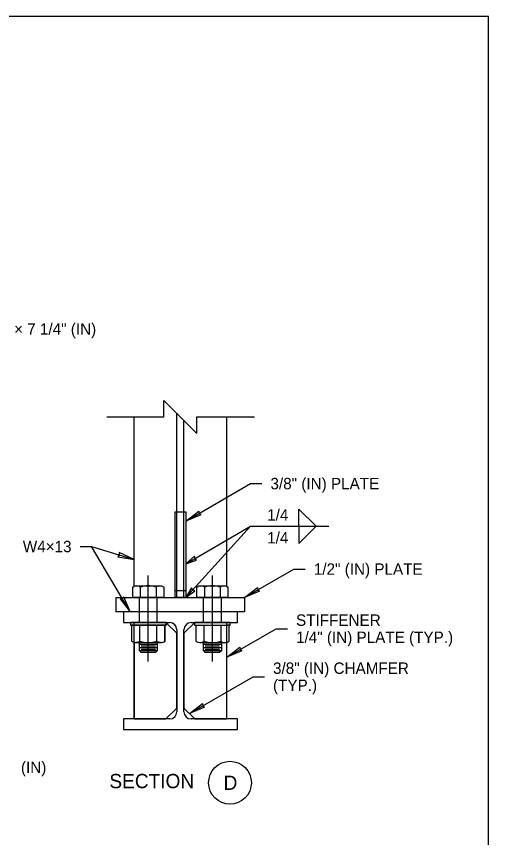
# Model space of a CAD drawing. Extents: x 99862 to 103151, y 100000 to 108076.
# Drawn here: x 102488 to 103151, y 103925 to 105076 of the extents above; entities that cross this region are included whole.
import ezdxf

# ---------------------------------------------------------------- set-up
doc = ezdxf.new("R2010")
doc.units = 0
for name, color, linetype in [('Level 1', 7, 'Continuous'), ('Level 13', 7, 'Continuous'), ('Level 15', 7, 'Continuous'), ('Level 20', 7, 'Continuous'), ('Level 30', 7, 'Continuous'), ('Level 34', 7, 'Continuous'), ('Level 35', 7, 'Continuous'), ('Level 36', 7, 'Continuous'), ('Level 60', 7, 'Continuous'), ('Level 9', 7, 'Continuous')]:
    doc.layers.add(name, color=color, linetype=linetype)

msp = doc.modelspace()

# ---------------------------------------------------------------- linework, layer by layer
at = {"layer": 'Level 1'}
msp.add_lwpolyline([(99862, 102999.5), (103151, 102999.5), (103151, 105075.5), (99862, 105075.5)], close=True, dxfattribs=at)
at = {"layer": 'Level 13'}
for p, q in [((102653.5, 104276.7), (102653.5, 104514.2)), ((102783.5, 104276.6), (102783.5, 104514.2)), ((102798.5, 104241), (102638.5, 104241)), ((102638.5, 104241), (102638.5, 104226)), ((102798.5, 104226), (102798.5, 104241)), ((102638.5, 104226), (102703.5, 104226)), ((102653.5, 104226), (102698.3, 104226)), ((102698.3, 104226), (102713.5, 104211)), ((102738.7, 104226), (102723.5, 104211)), ((102733.5, 104226), (102798.5, 104226)), ((102783.5, 104226), (102738.7, 104226)), ((102783.5, 104091), (102783.5, 104226)), ((102713.5, 104216), (102713.5, 104101)), ((102713.5, 104211), (102713.5, 104106)), ((102723.5, 104101), (102723.5, 104216)), ((102723.5, 104211), (102723.5, 104106)), ((102653.5, 104091), (102653.5, 104198.2)), ((102713.5, 104106), (102698.3, 104091)), ((102723.5, 104106), (102738.7, 104091)), ((102703.5, 104091), (102638.5, 104091)), ((102638.5, 104091), (102638.5, 104076)), ((102698.3, 104091), (102653.5, 104091)), ((102798.5, 104091), (102733.5, 104091)), ((102738.7, 104091), (102783.5, 104091)), ((102798.5, 104076), (102798.5, 104091)), ((102638.5, 104076), (102798.5, 104076))]:
    msp.add_line(p, q, dxfattribs=at)
for points in [[(102711, 104381), (102726, 104381), (102726, 104261), (102711, 104261)], [(102711, 104271), (102726, 104271), (102726, 104261), (102711, 104261)], [(102628.5, 104261), (102808.5, 104261), (102808.5, 104241), (102628.5, 104241)]]:
    msp.add_lwpolyline(points, close=True, dxfattribs=at)
for centre, start, end in [((102703.5, 104216), 0, 90), ((102733.5, 104216), 90, 180), ((102703.5, 104101), 270, 360), ((102733.5, 104101), 180, 270)]:
    msp.add_arc(centre, 10, start, end, dxfattribs=at)
at = {"layer": 'Level 15'}
for p, q in [((102726, 104368.3), (102816.9, 104420.8)), ((102816.9, 104420.8), (102832.9, 104420.8)), ((102726, 104308.5), (102816.7, 104360.9)), ((102816.7, 104360.9), (102726, 104261)), ((102577.9, 104332.6), (102593.9, 104332.6)), ((102808.5, 104261), (102877.8, 104301)), ((102877.8, 104301), (102893.8, 104301)), ((102673.5, 104171.5), (102673.5, 104292)), ((102763.5, 104171.5), (102763.5, 104292)), ((102783.5, 104177.4), (102852.8, 104217.4)), ((102852.8, 104217.4), (102868.8, 104217.4)), ((102731.1, 104098.5), (102820.5, 104150.1)), ((102820.5, 104150.1), (102836.5, 104150.1))]:
    msp.add_line(p, q, dxfattribs=at)
for points in [[(102615.5, 104514.2), (102695.3, 104514.2), (102695.3, 104537.4), (102741.7, 104491), (102741.7, 104514.2), (102822.3, 104514.2)], [(102648.1, 104241), (102593.9, 104332.6), (102653.5, 104314.6)]]:
    msp.add_lwpolyline(points, dxfattribs=at)
for points in [[(102726, 104368.3), (102744.3, 104382.3), (102744.8, 104379.2), (102747.2, 104377.1)], [(102653.5, 104314.6), (102632.5, 104324), (102632.6, 104320.9), (102630.8, 104318.3)], [(102726, 104308.5), (102741.1, 104313.7), (102739, 104316), (102738.1, 104319)], [(102726, 104261), (102738.8, 104270.5), (102736.1, 104272.1), (102734.3, 104274.7)], [(102808.5, 104261), (102826.8, 104275), (102827.3, 104271.9), (102829.7, 104269.8)], [(102648.1, 104241), (102639, 104262.1), (102637, 104259.7), (102633.9, 104259.1)], [(102783.5, 104177.4), (102801.8, 104191.4), (102802.3, 104188.3), (102804.7, 104186.2)], [(102731.1, 104098.5), (102749.4, 104112.5), (102749.9, 104109.4), (102752.3, 104107.3)]]:
    msp.add_lwpolyline(points, close=True, dxfattribs=at)
at = {"layer": 'Level 20'}
for p, q in [((102884.8, 104360.9), (102884.8, 104384.9)), ((102884.8, 104384.9), (102908.8, 104360.9)), ((102816.7, 104360.9), (102926.7, 104360.9)), ((102884.8, 104360.9), (102884.8, 104336.9)), ((102884.8, 104336.9), (102908.8, 104360.9))]:
    msp.add_line(p, q, dxfattribs=at)
at = {"layer": 'Level 30'}
for p, q in [((102662.7, 104261), (102662.7, 104275.5)), ((102684.3, 104275.5), (102684.3, 104261)), ((102752.7, 104261), (102752.7, 104275.5)), ((102774.3, 104275.5), (102774.3, 104261)), ((102661.8, 104199.8), (102661.8, 104222.6)), ((102685.2, 104222.6), (102685.2, 104199.8)), ((102655.9, 104198), (102691.1, 104198)), ((102661, 104195.6), (102686, 104195.6)), ((102661, 104190.9), (102686, 104190.9)), ((102686, 104186.2), (102661, 104186.2)), ((102663.3, 104193.3), (102683.6, 104193.3)), ((102663.3, 104188.6), (102683.6, 104188.6))]:
    msp.add_line(p, q, dxfattribs=at)
for points in [[(102692.2, 104277.4), (102695.1, 104275.7), (102695.1, 104261), (102651.8, 104261), (102651.8, 104275.7), (102654.7, 104277.4), (102692.2, 104277.4)], [(102782.2, 104277.4), (102785.1, 104275.7), (102785.1, 104261), (102741.8, 104261), (102741.8, 104275.7), (102744.7, 104277.4), (102782.2, 104277.4)], [(102648.5, 104226), (102648.5, 104222.6), (102698.5, 104222.6), (102698.5, 104226), (102648.5, 104226)], [(102696.9, 104199.8), (102696.9, 104222.6), (102650, 104222.6), (102650, 104199.8)], [(102783.5, 104222.6), (102788.5, 104222.6), (102788.5, 104226), (102783.5, 104226)], [(102786.9, 104199.8), (102786.9, 104222.6), (102783.5, 104222.6)], [(102686, 104198), (102686, 104186.2), (102683.6, 104183.9), (102663.3, 104183.9), (102661, 104186.2), (102661, 104198)]]:
    msp.add_lwpolyline(points, dxfattribs=at)
for centre, radius, start, end in [((102657.1, 104268.2), 9.17, 52.8251, 125.1741), ((102673.5, 104245), 32.4, 70.4632, 109.5368), ((102689.8, 104268.2), 9.17, 54.8259, 127.1749), ((102747.1, 104268.2), 9.17, 52.8251, 125.1741), ((102763.5, 104245), 32.4, 70.4632, 109.5368), ((102779.8, 104268.2), 9.17, 54.8259, 127.1749), ((102655.9, 104208.1), 10.2, 234.7356, 305.2644), ((102673.5, 104238.6), 40.6, 253.2213, 286.7787), ((102691.1, 104208.1), 10.2, 234.7356, 305.2644), ((102781.1, 104208.1), 10.2, 283.7077, 305.2644)]:
    msp.add_arc(centre, radius, start, end, dxfattribs=at)
at = {"layer": 'Level 34'}
for p, q in [((102713.5, 104106), (102713.5, 104211)), ((102661, 104198), (102656.1, 104198)), ((102690.8, 104198), (102686, 104198)), ((102653.5, 104091), (102698.3, 104091))]:
    msp.add_line(p, q, dxfattribs=at)
for points in [[(102711, 104381), (102726, 104381), (102726, 104261), (102711, 104261)], [(102723.5, 104211), (102723.5, 104106), (102738.7, 104091), (102783.5, 104091), (102783.5, 104226), (102738.7, 104226)]]:
    msp.add_lwpolyline(points, close=True, dxfattribs=at)
for points in [[(102698.5, 104225.8), (102698.5, 104222.6), (102696.9, 104222.6)], [(102696.9, 104222.6), (102696.9, 104199.8)], [(102713.5, 104211), (102698.5, 104225.8)], [(102653.5, 104198.2), (102653.5, 104091)], [(102686, 104198), (102686, 104186.2), (102683.6, 104183.9), (102663.3, 104183.9), (102661, 104186.2), (102661, 104198)], [(102698.3, 104091), (102713.5, 104106)]]:
    msp.add_lwpolyline(points, dxfattribs=at)
for centre, start, end in [((102655.9, 104208.1), 256.2808, 271.2774), ((102691.1, 104208.1), 268.7226, 305.2644)]:
    msp.add_arc(centre, 10.2, start, end, dxfattribs=at)
at = {"layer": 'Level 35'}
for p, q in [((102740, 104222.6), (102740, 104199.8)), ((102751.8, 104199.8), (102751.8, 104222.6)), ((102775.2, 104222.6), (102775.2, 104199.8)), ((102745.9, 104198), (102781.1, 104198)), ((102751, 104195.6), (102776, 104195.6)), ((102751, 104190.9), (102776, 104190.9)), ((102776, 104186.2), (102751, 104186.2)), ((102753.3, 104193.3), (102773.6, 104193.3)), ((102753.3, 104188.6), (102773.6, 104188.6))]:
    msp.add_line(p, q, dxfattribs=at)
for points in [[(102738.5, 104226), (102738.5, 104222.6), (102783.5, 104222.6)], [(102783.5, 104226), (102738.5, 104226)], [(102776, 104198), (102776, 104186.2), (102773.6, 104183.9), (102753.3, 104183.9), (102751, 104186.2), (102751, 104198)]]:
    msp.add_lwpolyline(points, dxfattribs=at)
for centre, radius, start, end in [((102745.9, 104208.1), 10.2, 234.7356, 305.2644), ((102763.5, 104238.6), 40.6, 253.2213, 286.7787), ((102781.1, 104208.1), 10.2, 234.7356, 283.7077)]:
    msp.add_arc(centre, radius, start, end, dxfattribs=at)
at = {"layer": 'Level 36'}
for p, q in [((102713.5, 104261), (102713.5, 104519.2)), ((102723.5, 104261), (102723.5, 104509.2)), ((102661, 104226), (102661, 104261)), ((102686, 104226), (102686, 104261)), ((102751, 104226), (102751, 104261)), ((102776, 104226), (102776, 104261)), ((102653.5, 104198.2), (102653.5, 104226))]:
    msp.add_line(p, q, dxfattribs=at)
at = {"layer": 'Level 60'}
msp.add_line((103151, 105075.5), (103151, 105075.5), dxfattribs=at)
at = {"layer": 'Level 9'}
msp.add_circle((102788.1, 104001.6), 30, dxfattribs=at)

# ---------------------------------------------------------------- texts
at = {"layer": 'Level 20'}
for s, height, p in [('1/2" (IN) × 4 1/2" (IN) × 7 1/4" (IN)', 16, (102279.1, 104629.4)), ('3/8" (IN) PLATE', 16, (102844.9, 104412.8)), ('1/4', 16, (102840.3, 104368.9)), ('1/4', 16, (102840.3, 104336.9)), ('W4×13', 16, (102497.4, 104324.6)), ('1/2" (IN) PLATE', 16, (102905.8, 104293)), ('STIFFENER', 16, (102880.8, 104221.4)), ('1/4" (IN) PLATE (TYP.)', 16, (102880.8, 104197.4)), ('3/8" (IN) CHAMFER', 16, (102848.5, 104154.1)), ('(TYP.)', 16, (102848.5, 104130.1)), (' (IN)', 16, (102488.8, 104015.2)), ('SECTION', 20, (102618.9, 103993.9)), ('D', 20, (102779.1, 103991.5))]:
    msp.add_text(s, height=height, dxfattribs=at).set_placement(p)

doc.saveas('drawing.dxf')
